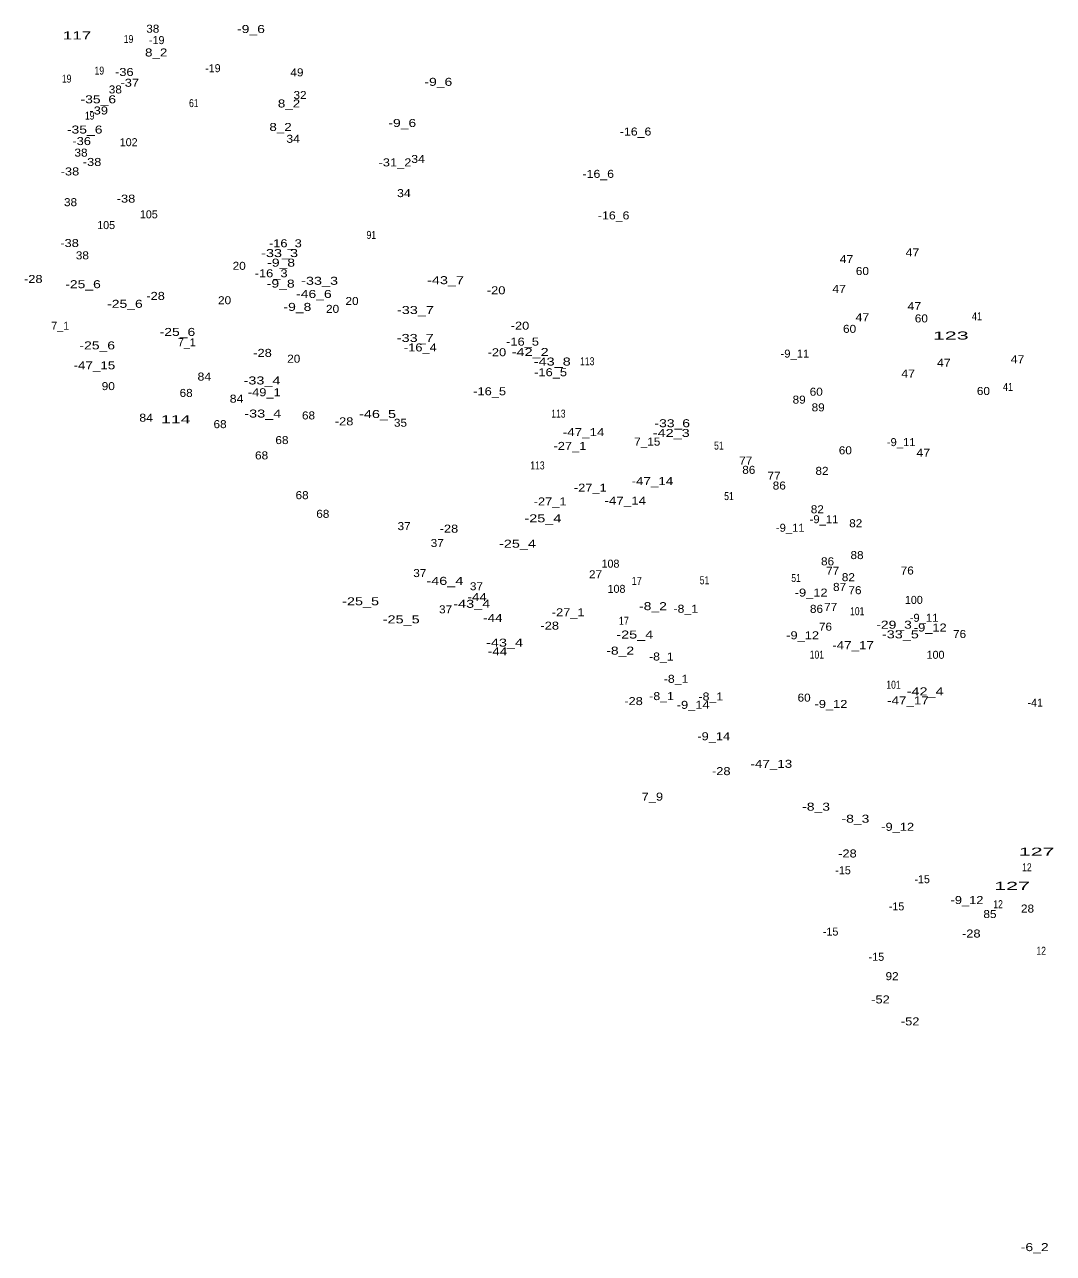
# Model space of a CAD drawing. Extents: x -663705 to -661666, y -1002081 to -999269.
# Drawn here: x -663640 to -663126, y -1001199 to -1000585 of the extents above; entities that cross this region are included whole.
import ezdxf
from ezdxf.enums import TextEntityAlignment as Align

# ---------------------------------------------------------------- set-up
doc = ezdxf.new("R2010")
doc.units = 0
doc.header["$LTSCALE"] = 1.6
doc.layers.add('24', color=7, linetype='Continuous')

msp = doc.modelspace()

# ---------------------------------------------------------------- texts
at = {"layer": '24'}
for s, width, p in [('117', 1.6, (-663614.259, -1000592.14)), ('19', 0.8, (-663588.49, -1000593.96)), ('38', 1.1, (-663576.39, -1000588.8)), ('-9_6', 1.3, (-663527.31, -1000588.97)), ('8_2', 1.25, (-663574.69, -1000600.69)), ('19', 0.8, (-663603.101, -1000609.73)), ('-36', 1.2, (-663590.61, -1000610.43)), ('49', 1.1, (-663504.34, -1000610.6)), ('19', 0.8, (-663619.441, -1000613.77)), ('-37', 1.2, (-663587.9, -1000615.81)), ('-9_6', 1.3, (-663433.68, -1000615.35)), ('-35_6', 1.3, (-663603.62, -1000624.08)), ('38', 1.1, (-663595.11, -1000619.15)), ('32', 1.1, (-663502.79, -1000621.93)), ('-39', 1.2, (-663603.41, -1000629.67)), ('61', 0.8, (-663555.89, -1000625.97)), ('8_2', 1.25, (-663508.31, -1000626.17)), ('19', 0.8, (-663607.91, -1000632.23)), ('-9_6', 1.3, (-663451.7, -1000635.9)), ('-35_6', 1.3, (-663610.41, -1000639.2)), ('8_2', 1.25, (-663512.54, -1000637.9)), ('-16_6', 1.15, (-663335.09, -1000640.19)), ('-36', 1.2, (-663611.94, -1000644.95)), ('34', 1.15, (-663506.24, -1000643.81)), ('38', 1.1, (-663612.26, -1000650.72)), ('-38', 1.2, (-663606.73, -1000655.38)), ('-31_2', 1.2, (-663455.35, -1000655.61)), ('34', 1.15, (-663443.809, -1000653.89)), ('-38', 1.2, (-663617.78, -1000660.13)), ('-16_6', 1.15, (-663353.74, -1000661.34)), ('-38', 1.2, (-663589.76, -1000673.71)), ('34', 1.15, (-663450.89, -1000670.96)), ('38', 1.1, (-663617.49, -1000675.49)), ('-16_6', 1.15, (-663346.05, -1000682.11)), ('91', 0.8, (-663467.171, -1000691.84)), ('-38', 1.2, (-663617.97, -1000695.91)), ('-16_3', 1.2, (-663510.12, -1000696.02)), ('38', 1.1, (-663611.579, -1000702.06)), ('-33_3', 1.35, (-663513.01, -1000700.92)), ('47', 1.15, (-663229.69, -1000703.93)), ('47', 1.15, (-663196.74, -1000700.63)), ('20', 1.1, (-663533.199, -1000707.29)), ('-16_3', 1.2, (-663517.24, -1000711.02)), ('-9_8', 1.3, (-663512.25, -1000705.7)), ('60', 1.1, (-663221.74, -1000709.91)), ('-28', 1.2, (-663636.11, -1000713.86)), ('-25_6', 1.3, (-663611.25, -1000716.47)), ('-9_8', 1.3, (-663512.44, -1000716.17)), ('-33_3', 1.35, (-663493.02, -1000714.77)), ('-43_7', 1.35, (-663430.069, -1000714.46)), ('-28', 1.2, (-663574.98, -1000722.32)), ('-46_6', 1.3, (-663495.87, -1000721.35)), ('-20', 1.2, (-663404.79, -1000719.52)), ('47', 1.15, (-663233.38, -1000718.83)), ('-25_6', 1.3, (-663590.3, -1000726.28)), ('20', 1.1, (-663540.5, -1000724.5)), ('-9_8', 1.3, (-663504.11, -1000727.81)), ('20', 1.1, (-663486.52, -1000728.8)), ('20', 1.1, (-663476.809, -1000724.86)), ('-33_7', 1.35, (-663445.12, -1000729.38)), ('47', 1.15, (-663195.77, -1000727.4)), ('47', 1.15, (-663221.74, -1000732.98)), ('60', 1.1, (-663192.28, -1000733.57)), ('41', 0.85, (-663164.47, -1000732.47)), ('-25_6', 1.3, (-663564.06, -1000740.32)), ('-20', 1.2, (-663392.87, -1000737.21)), ('60', 1.1, (-663228.14, -1000738.78)), ('-25_6', 1.3, (-663604.14, -1000747.05)), ('-33_7', 1.35, (-663445.22, -1000743.33)), ('-16_5', 1.2, (-663391.591, -1000745.17)), ('123', 2, (-663177.577, -1000742.12)), ('-28', 1.2, (-663521.54, -1000750.79)), ('20', 1.1, (-663505.929, -1000753.71)), ('-16_4', 1.2, (-663442.67, -1000748.07)), ('-20', 1.2, (-663404.41, -1000750.48)), ('-42_2', 1.35, (-663387.78, -1000750.37)), ('-9_11', 1.05, (-663255.481, -1000751.16)), ('47', 1.15, (-663144.2, -1000753.97)), ('-47_15', 1.25, (-663605.56, -1000757.01)), ('-43_8', 1.35, (-663376.73, -1000755.12)), ('113', 0.8, (-663359.23, -1000754.97)), ('47', 1.15, (-663181.03, -1000755.71)), ('84', 1.15, (-663550.61, -1000762.63)), ('-33_4', 1.35, (-663521.79, -1000764.58)), ('-16_5', 1.2, (-663377.561, -1000760.46)), ('47', 1.15, (-663198.87, -1000761.11)), ('90', 1.1, (-663598.63, -1000767.4)), ('68', 1.1, (-663559.72, -1000770.8)), ('-49_1', 1.2, (-663520.67, -1000770.46)), ('-16_5', 1.2, (-663408.03, -1000769.98)), ('60', 1.1, (-663244.811, -1000770.2)), ('60', 1.1, (-663161.26, -1000769.83)), ('41', 0.85, (-663148.959, -1000767.77)), ('84', 1.15, (-663534.51, -1000773.68)), ('89', 1.1, (-663253.35, -1000774.15)), ('89', 1.1, (-663243.85, -1000778.02)), ('84', 1.15, (-663579.689, -1000783.18)), ('114', 1.65, (-663564.909, -1000783.98)), ('-33_4', 1.35, (-663521.41, -1000781.11)), ('68', 1.1, (-663498.56, -1000782.05)), ('-46_5', 1.35, (-663464.06, -1000781.33)), ('113', 0.8, (-663373.67, -1000781.15)), ('68', 1.1, (-663542.76, -1000786.41)), ('-28', 1.2, (-663480.78, -1000785.02)), ('35', 1.1, (-663452.6, -1000785.7)), ('-47_14', 1.25, (-663361.079, -1000790.41)), ('-42_3', 1.35, (-663317.27, -1000790.8)), ('-33_6', 1.3, (-663316.78, -1000785.95)), ('68', 1.1, (-663511.84, -1000794.36)), ('7_15', 1.1, (-663329.26, -1000795.14)), ('-9_11', 1.05, (-663202.361, -1000795.38)), ('68', 1.1, (-663522.01, -1000802.02)), ('-27_1', 1.2, (-663367.91, -1000797.29)), ('51', 0.8, (-663293.47, -1000797.14)), ('60', 1.1, (-663230.27, -1000799.48)), ('47', 1.15, (-663191.31, -1000800.67)), ('113', 0.8, (-663384.14, -1000807.03)), ('77', 1.1, (-663280.03, -1000804.59)), ('86', 1.1, (-663278.51, -1000809.24)), ('-47_14', 1.25, (-663326.689, -1000814.84)), ('77', 1.1, (-663265.88, -1000812.16)), ('82', 1.1, (-663241.929, -1000809.74)), ('-27_1', 1.2, (-663357.72, -1000818.15)), ('86', 1.1, (-663263.29, -1000817.09)), ('68', 1.1, (-663501.76, -1000821.9)), ('-27_1', 1.2, (-663377.81, -1000825.03)), ('-47_14', 1.25, (-663340.24, -1000824.64)), ('51', 0.8, (-663288.429, -1000822.35)), ('68', 1.1, (-663491.41, -1000831.21)), ('-25_4', 1.35, (-663381.43, -1000833.46)), ('-9_11', 1.05, (-663240.941, -1000833.91)), ('82', 1.1, (-663244.26, -1000828.94)), ('37', 1.1, (-663450.79, -1000837.35)), ('-28', 1.2, (-663428.38, -1000838.63)), ('-9_11', 1.05, (-663257.811, -1000838.18)), ('82', 1.1, (-663225.059, -1000835.92)), ('37', 1.1, (-663434.21, -1000845.79)), ('-25_4', 1.35, (-663394.12, -1000846.15)), ('88', 1.1, (-663224.419, -1000851.84)), ('86', 1.1, (-663239.14, -1000854.95)), ('37', 1.1, (-663442.94, -1000860.82)), ('27', 1.1, (-663355.1, -1000861.43)), ('51', 0.8, (-663300.64, -1000864.43)), ('51', 0.8, (-663254.89, -1000863.27)), ('77', 1.1, (-663236.601, -1000859.67)), ('82', 1.1, (-663228.75, -1000862.88)), ('76', 1.1, (-663199.34, -1000859.55)), ('-46_4', 1.35, (-663430.41, -1000864.73)), ('37', 1.1, (-663414.63, -1000867.41)), ('17', 0.85, (-663334.5, -1000864.75)), ('-9_12', 1.2, (-663247.341, -1000870.58)), ('87', 1.1, (-663233.14, -1000867.74)), ('76', 1.1, (-663225.46, -1000869.39)), ('-25_5', 1.35, (-663472.52, -1000874.92)), ('-43_4', 1.35, (-663416.97, -1000876.19)), ('-44', 1.25, (-663414.26, -1000872.79)), ('37', 1.1, (-663430.04, -1000878.95)), ('-27_1', 1.2, (-663368.78, -1000880.41)), ('-8_2', 1.3, (-663326.41, -1000877.36)), ('-8_1', 1.15, (-663310, -1000878.66)), ('86', 1.1, (-663244.68, -1000878.7)), ('77', 1.1, (-663237.571, -1000877.71)), ('101', 0.8, (-663224.33, -1000879.87)), ('-25_5', 1.35, (-663452.24, -1000883.96)), ('-44', 1.25, (-663406.41, -1000883.26)), ('-28', 1.2, (-663378.01, -1000887.1)), ('17', 0.85, (-663340.941, -1000884.66)), ('76', 1.1, (-663240.2, -1000887.62)), ('-29_3', 1.3, (-663205.93, -1000886.63)), ('-9_11', 1.05, (-663190.931, -1000883.17)), ('-9_12', 1.2, (-663187.821, -1000888.04)), ('-25_4', 1.35, (-663335.49, -1000891.54)), ('-9_12', 1.2, (-663251.611, -1000891.9)), ('-33_5', 1.35, (-663202.76, -1000891.44)), ('76', 1.1, (-663173.17, -1000891.26)), ('-43_4', 1.35, (-663400.59, -1000895.58)), ('-44', 1.25, (-663404.079, -1000899.94)), ('-8_2', 1.3, (-663342.79, -1000899.57)), ('-47_17', 1.25, (-663226.4, -1000896.85)), ('-8_1', 1.15, (-663322.22, -1000902.52)), ('101', 0.8, (-663244.49, -1000901.59)), ('-8_1', 1.15, (-663314.85, -1000913.67)), ('101', 0.8, (-663206.2, -1000916.62)), ('-28', 1.2, (-663336.11, -1000924.79)), ('-8_1', 1.15, (-663322.12, -1000922.3)), ('-8_1', 1.15, (-663297.5, -1000922.49)), ('60', 1.1, (-663250.87, -1000923.06)), ('-47_17', 1.25, (-663198.99, -1000924.49)), ('-42_4', 1.35, (-663190.38, -1000919.94)), ('-9_14', 1.2, (-663306.31, -1000926.66)), ('-9_12', 1.2, (-663237.451, -1000926.23)), ('-9_14', 1.2, (-663296.04, -1000942.37)), ('-47_13', 1.25, (-663267.24, -1000956.15)), ('-28', 1.2, (-663292.28, -1000959.79)), ('7_9', 1.2, (-663326.7, -1000972.54)), ('-8_3', 1.3, (-663244.88, -1000977.56)), ('-8_3', 1.3, (-663225.22, -1000983.57)), ('-9_12', 1.2, (-663204.111, -1000987.61)), ('-28', 1.2, (-663229.22, -1001000.94)), ('127', 2, (-663134.653, -1001000.03)), ('12', 0.8, (-663139.51, -1001007.83)), ('127', 2, (-663146.933, -1001017.11)), ('-9_12', 1.2, (-663169.461, -1001024.21)), ('12', 0.8, (-663153.919, -1001026.29)), ('28', 1.1, (-663139.209, -1001028.46)), ('85', 1.1, (-663157.99, -1001031.21)), ('-28', 1.2, (-663167.32, -1001040.94)), ('12', 0.8, (-663132.39, -1001049.56)), ('92', 1.1, (-663206.9, -1001062.25)), ('-52', 1.2, (-663212.7, -1001073.88)), ('-52', 1.2, (-663197.87, -1001084.84)), ('-6_2', 1.3, (-663135.62, -1001197.64))]:
    msp.add_text(s, height=4, dxfattribs=dict(at, width=width)).set_placement(p, align=Align.CENTER)
for s, p in [('-19', (-663574.42, -1000594.5)), ('-19', (-663546.35, -1000608.54)), ('102', (-663588.44, -1000645.51)), ('105', (-663578.37, -1000681.55)), ('105', (-663599.7, -1000686.93)), ('7_1', (-663622.669, -1000737.25)), ('7_1', (-663559.38, -1000745.5)), ('108', (-663347.64, -1000856.11)), ('108', (-663344.63, -1000868.71)), ('100', (-663196.03, -1000874.22)), ('100', (-663185.18, -1000901.66)), ('-41', (-663135.35, -1000925.57)), ('-15', (-663231.41, -1001009.33)), ('-15', (-663191.861, -1001013.79)), ('-15', (-663204.66, -1001027.37)), ('-15', (-663237.611, -1001039.98)), ('-15', (-663214.74, -1001052.58))]:
    msp.add_text(s, height=4, dxfattribs=at).set_placement(p, align=Align.CENTER)

doc.saveas('drawing.dxf')
